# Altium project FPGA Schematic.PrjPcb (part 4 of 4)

## Sheet EVRHC008_VOUT_A_Phases 1-2-3.SchDoc
size 431 x 279 mm; Date: Not shown in title block; ApprovedBy: Not shown in title block; CheckedBy: Not shown in title block; Author: Not shown in title block; CompanyName: Not shown in title block; Engineer: Not shown in title block; Organization: Not shown in title block; Address1: Not shown in title block; Address2: Not shown in title block; Address3: Not shown in title block; Address4: Not shown in title block; DocumentNumber: 4; Revision: Use project parameter SCH_Rev; SheetNumber: 4; SheetTotal: 17; PageSetup: Record=PageOptions¦CenterHorizontal=True¦CenterVertical=True¦PrintScale=1.00¦XCorrection=1.00¦YCorrection=1.00¦PrintKind=0¦BorderSize=5000000¦LeftOffset=0¦BottomOffset=0¦Orientation=2¦PaperLength=1000¦PaperWidth=1000¦Scale=100¦PaperSource=15¦PrintQuality=600¦MediaType=1¦DitherType=10¦PaperKind=Letter¦PrintScaleMode=1
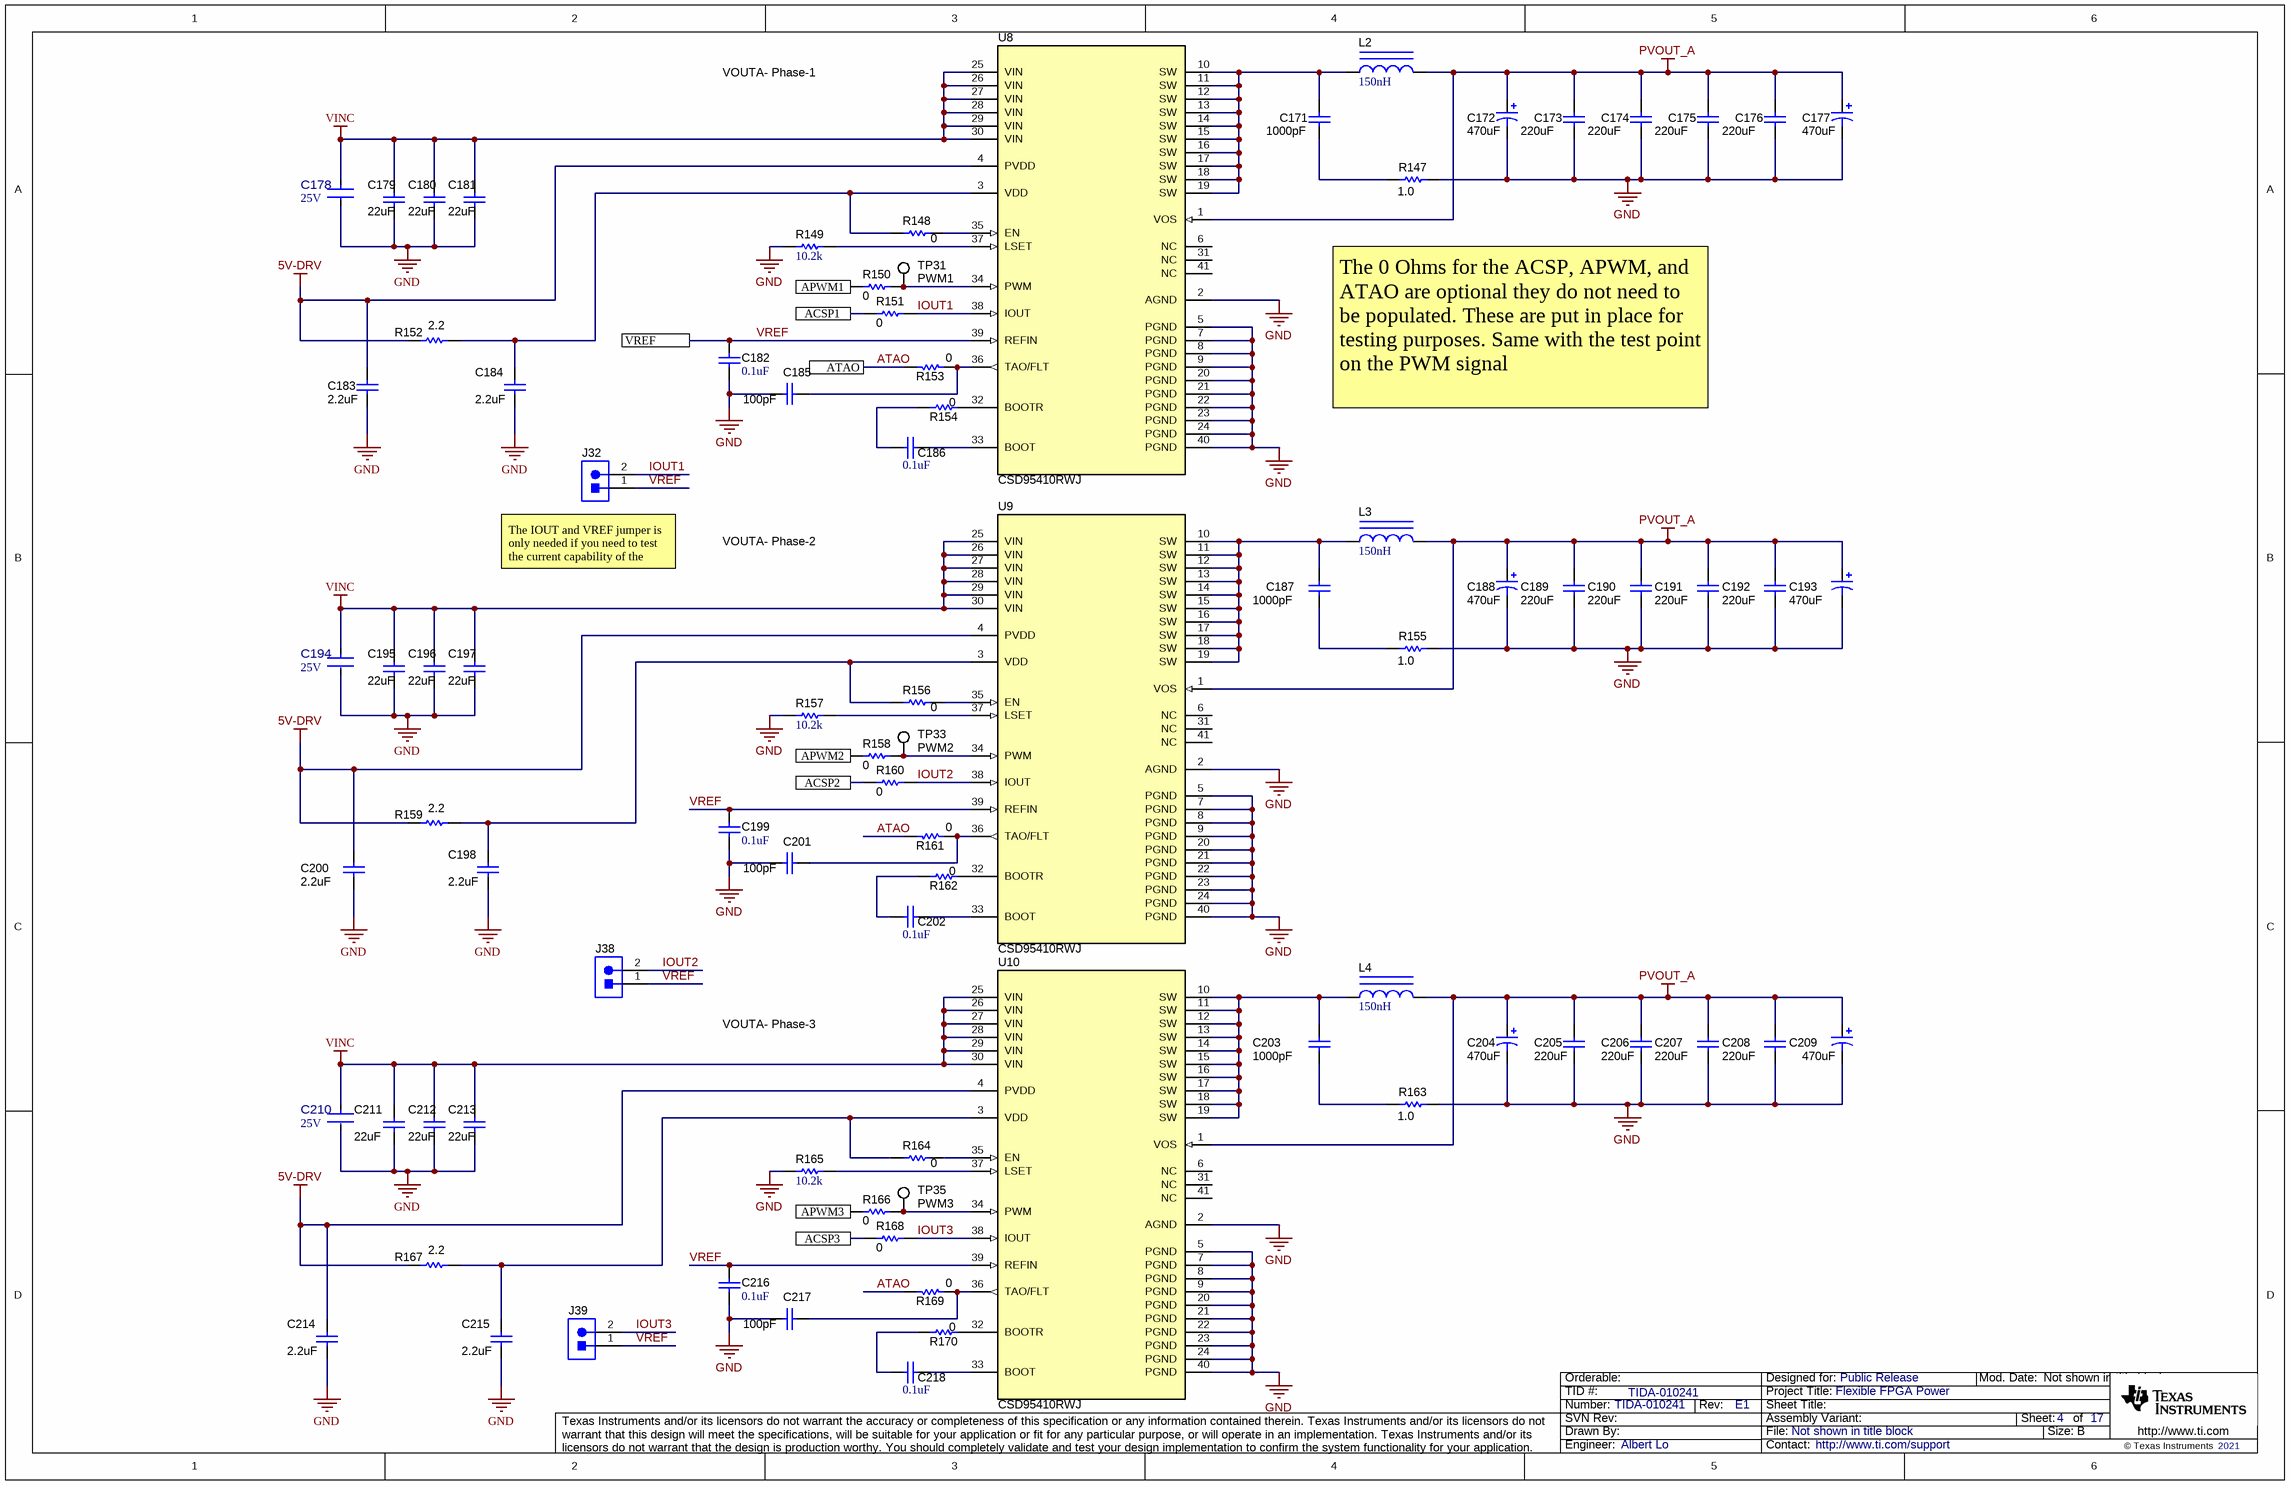
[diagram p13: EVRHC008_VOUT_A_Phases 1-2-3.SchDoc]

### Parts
C171  ValueDisplayed: 1000pF  [0402S]  (hidden comment: GRM155R71H102KA01D)
C172  ValueDisplayed: 470uF  [GX_2TERM]  (hidden comment: EEF-GX0E471R)
C173  ValueDisplayed: 220uF  [1206_190L]  (hidden comment: GRM31CR60G227ME11L)
C174  ValueDisplayed: 220uF  [1206_190L]  (hidden comment: GRM31CR60G227ME11L)
C175  ValueDisplayed: 220uF  [1206_190L]  (hidden comment: GRM31CR60G227ME11L)
C176  ValueDisplayed: 220uF  [1206_190L]  (hidden comment: GRM31CR60G227ME11L)
C177  ValueDisplayed: 470uF  [GX_2TERM]  (hidden comment: EEF-GX0E471R)
C178  VDC_V: 25V  [FP-GRM155C81E105KE11D_0402-MFG]  (hidden comment: GRM155C81E105KE11D)
C179  ValueDisplayed: 22uF  [0805L]  (hidden comment: Capacitor)
C180  ValueDisplayed: 22uF  [0805L]  (hidden comment: Capacitor)
C181  ValueDisplayed: 22uF  [0805L]  (hidden comment: Capacitor)
C182  ValueDisplayed: 0.1uF  [0402S]  (hidden comment: GCM155R71H104KE02D)
C183  ValueDisplayed: 2.2uF  [0402S]  (hidden comment: Capacitor)
C184  ValueDisplayed: 2.2uF  [0402S]  (hidden comment: Capacitor)
C185  ValueDisplayed: 100pF  [0402S]  (hidden comment: Capacitor)
C186  ValueDisplayed: 0.1uF  [0402S]  (hidden comment: GCM155R71H104KE02D)
C187  ValueDisplayed: 1000pF  [0402S]  (hidden comment: GRM155R71H102KA01D)
C188  ValueDisplayed: 470uF  [GX_2TERM]  (hidden comment: EEF-GX0E471R)
C189  ValueDisplayed: 220uF  [1206_190L]  (hidden comment: GRM31CR60G227ME11L)
C190  ValueDisplayed: 220uF  [1206_190L]  (hidden comment: GRM31CR60G227ME11L)
C191  ValueDisplayed: 220uF  [1206_190L]  (hidden comment: GRM31CR60G227ME11L)
C192  ValueDisplayed: 220uF  [1206_190L]  (hidden comment: GRM31CR60G227ME11L)
C193  ValueDisplayed: 470uF  [GX_2TERM]  (hidden comment: EEF-GX0E471R)
C194  VDC_V: 25V  [FP-GRM155C81E105KE11D_0402-MFG]  (hidden comment: GRM155C81E105KE11D)
C195  ValueDisplayed: 22uF  [0805L]  (hidden comment: Capacitor)
C196  ValueDisplayed: 22uF  [0805L]  (hidden comment: Capacitor)
C197  ValueDisplayed: 22uF  [0805L]  (hidden comment: Capacitor)
C198  ValueDisplayed: 2.2uF  [0402S]  (hidden comment: Capacitor)
C199  ValueDisplayed: 0.1uF  [0402S]  (hidden comment: GCM155R71H104KE02D)
C200  ValueDisplayed: 2.2uF  [0402S]  (hidden comment: Capacitor)
C201  ValueDisplayed: 100pF  [0402S]  (hidden comment: Capacitor)
C202  ValueDisplayed: 0.1uF  [0402S]  (hidden comment: GCM155R71H104KE02D)
C203  ValueDisplayed: 1000pF  [0402S]  (hidden comment: GRM155R71H102KA01D)
C204  ValueDisplayed: 470uF  [GX_2TERM]  (hidden comment: EEF-GX0E471R)
C205  ValueDisplayed: 220uF  [1206_190L]  (hidden comment: GRM31CR60G227ME11L)
C206  ValueDisplayed: 220uF  [1206_190L]  (hidden comment: GRM31CR60G227ME11L)
C207  ValueDisplayed: 220uF  [1206_190L]  (hidden comment: GRM31CR60G227ME11L)
C208  ValueDisplayed: 220uF  [1206_190L]  (hidden comment: GRM31CR60G227ME11L)
C209  ValueDisplayed: 470uF  [GX_2TERM]  (hidden comment: EEF-GX0E471R)
C210  VDC_V: 25V  [FP-GRM155C81E105KE11D_0402-MFG]  (hidden comment: GRM155C81E105KE11D)
C211  ValueDisplayed: 22uF  [0805L]  (hidden comment: Capacitor)
C212  ValueDisplayed: 22uF  [0805L]  (hidden comment: Capacitor)
C213  ValueDisplayed: 22uF  [0805L]  (hidden comment: Capacitor)
C214  ValueDisplayed: 2.2uF  [0402S]  (hidden comment: Capacitor)
C215  ValueDisplayed: 2.2uF  [0402S]  (hidden comment: Capacitor)
C216  ValueDisplayed: 0.1uF  [0402S]  (hidden comment: GCM155R71H104KE02D)
C217  ValueDisplayed: 100pF  [0402S]  (hidden comment: Capacitor)
C218  ValueDisplayed: 0.1uF  [0402S]  (hidden comment: GCM155R71H104KE02D)
J32  TSW-102-07-G-S  [TSW-102-07-G-S]  (value not drawn)
J38  TSW-102-07-G-S  [TSW-102-07-G-S]  (value not drawn)
J39  TSW-102-07-G-S  [TSW-102-07-G-S]  (value not drawn)
L2  ValueDisplayed: 150nH  [SLR1050]  (hidden comment: SLR1050A-151KEB)
L3  ValueDisplayed: 150nH  [SLR1050]  (hidden comment: SLR1050A-151KEB)
L4  ValueDisplayed: 150nH  [SLR1050]  (hidden comment: SLR1050A-151KEB)
R147  ValueDisplayed: 1.0  [0603S]  (hidden comment: CRCW06031R00JNEA)
R148  ValueDisplayed: 0  [0402S]  (hidden comment: CRCW04020000Z0ED)
R149  ValueDisplayed: 10.2k  [0402S]  (hidden comment: ERA-2AEB1022X)
R150  ValueDisplayed: 0  [0402S]  (hidden comment: CRCW04020000Z0ED)
R151  ValueDisplayed: 0  [0402S]  (hidden comment: CRCW04020000Z0ED)
R152  value 2.2  [0402S]  (hidden comment: CRCW04022R20JNED)
R153  ValueDisplayed: 0  [0402S]  (hidden comment: CRCW04020000Z0ED)
R154  value 0  [0402S]  (hidden comment: CRCW04020000Z0ED)
R155  ValueDisplayed: 1.0  [0603S]  (hidden comment: CRCW06031R00JNEA)
R156  ValueDisplayed: 0  [0402S]  (hidden comment: CRCW04020000Z0ED)
R157  ValueDisplayed: 10.2k  [0402S]  (hidden comment: ERA-2AEB1022X)
R158  ValueDisplayed: 0  [0402S]  (hidden comment: CRCW04020000Z0ED)
R159  value 2.2  [0402S]  (hidden comment: CRCW04022R20JNED)
R160  ValueDisplayed: 0  [0402S]  (hidden comment: CRCW04020000Z0ED)
R161  ValueDisplayed: 0  [0402S]  (hidden comment: CRCW04020000Z0ED)
R162  value 0  [0402S]  (hidden comment: CRCW04020000Z0ED)
R163  ValueDisplayed: 1.0  [0603S]  (hidden comment: CRCW06031R00JNEA)
R164  ValueDisplayed: 0  [0402S]  (hidden comment: CRCW04020000Z0ED)
R165  ValueDisplayed: 10.2k  [0402S]  (hidden comment: ERA-2AEB1022X)
R166  ValueDisplayed: 0  [0402S]  (hidden comment: CRCW04020000Z0ED)
R167  value 2.2  [0402S]  (hidden comment: CRCW04022R20JNED)
R168  ValueDisplayed: 0  [0402S]  (hidden comment: CRCW04020000Z0ED)
R169  ValueDisplayed: 0  [0402S]  (hidden comment: CRCW04020000Z0ED)
R170  value 0  [0402S]  (hidden comment: CRCW04020000Z0ED)
TP31  PWM1  [Keystone5007]
TP33  PWM2  [Keystone5007]
TP35  PWM3  [Keystone5007]
U8  CSD95410RWJ  [RWJ0041A]
U9  CSD95410RWJ  [RWJ0041A]
U10  CSD95410RWJ  [RWJ0041A]

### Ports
ACSP1, ACSP2, ACSP3, APWM1, APWM2, APWM3, ATAO, VREF

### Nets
5V-DRV: C183.1 C200.1 C214.1 R152.1 R159.1 R167.1 U8.4(PVDD) U9.4(PVDD) U10.4(PVDD)
GND: C172.2(-) C173.2 C174.2 C175.2 C176.2 C177.2(-) C178.2 C179.2 C180.2 C181.2 C182.1 C183.2 C184.2 C185.1 C188.2(-) C189.2 C190.2 C191.2 C192.2 C193.2(-) C194.2 C195.2 C196.2 C197.2 C198.2 C199.1 C200.2 C201.1 C204.2(-) C205.2 C206.2 C207.2 C208.2 C209.2(-) C210.2 C211.2 C212.2 C213.2 C214.2 C215.2 C216.1 C217.1 R147.1 R149.1 R155.1 R157.1 R163.1 R165.1 U8.2(AGND) U8.5(PGND) U8.7(PGND) U8.8(PGND) U8.9(PGND) U8.20(PGND) U8.21(PGND) U8.22(PGND) U8.23(PGND) U8.24(PGND) U8.40(PGND) U9.2(AGND) U9.5(PGND) U9.7(PGND) U9.8(PGND) U9.9(PGND) U9.20(PGND) U9.21(PGND) U9.22(PGND) U9.23(PGND) U9.24(PGND) U9.40(PGND) U10.2(AGND) U10.5(PGND) U10.7(PGND) U10.8(PGND) U10.9(PGND) U10.20(PGND) U10.21(PGND) U10.22(PGND) U10.23(PGND) U10.24(PGND) U10.40(PGND)
PVOUT_A: C172.1(+) C173.1 C174.1 C175.1 C176.1 C177.1(+) C188.1(+) C189.1 C190.1 C191.1 C192.1 C193.1(+) C204.1(+) C205.1 C206.1 C207.1 C208.1 C209.1(+) L2.2 L3.2 L4.2 U8.1(VOS) U9.1(VOS) U10.1(VOS)
VINC: C178.1 C179.1 C180.1 C181.1 C194.1 C195.1 C196.1 C197.1 C210.1 C211.1 C212.1 C213.1 U8.25(VIN) U8.26(VIN) U8.27(VIN) U8.28(VIN) U8.29(VIN) U8.30(VIN) U9.25(VIN) U9.26(VIN) U9.27(VIN) U9.28(VIN) U9.29(VIN) U9.30(VIN) U10.25(VIN) U10.26(VIN) U10.27(VIN) U10.28(VIN) U10.29(VIN) U10.30(VIN)
ACSP1: R151.2 ; port ACSP1
ACSP2: R160.2 ; port ACSP2
ACSP3: R168.2 ; port ACSP3
APWM1: R150.2 ; port APWM1
APWM2: R158.2 ; port APWM2
APWM3: R166.2 ; port APWM3
ATAO: R153.1 R161.1 R169.1 ; port ATAO
IOUT1: J32.2 R151.1 U8.38(IOUT)
IOUT2: J38.2 R160.1 U9.38(IOUT)
IOUT3: J39.2 R168.1 U10.38(IOUT)
VREF: C182.2 C199.2 C216.2 J32.1 J38.1 J39.1 U8.39(REFIN) U9.39(REFIN) U10.39(REFIN) ; port VREF
NetC171_1: C171.1 L2.1 U8.10(SW) U8.11(SW) U8.12(SW) U8.13(SW) U8.14(SW) U8.15(SW) U8.16(SW) U8.17(SW) U8.18(SW) U8.19(SW)
NetC171_2: C171.2 R147.2
NetC184_1: C184.1 R148.2 R152.2 U8.3(VDD)
NetC185_2: C185.2 R153.2 U8.36(TAO/FLT)
NetC186_1: C186.1 R154.2
NetC186_2: C186.2 U8.33(BOOT)
NetC187_1: C187.1 L3.1 U9.10(SW) U9.11(SW) U9.12(SW) U9.13(SW) U9.14(SW) U9.15(SW) U9.16(SW) U9.17(SW) U9.18(SW) U9.19(SW)
NetC187_2: C187.2 R155.2
NetC198_1: C198.1 R156.2 R159.2 U9.3(VDD)
NetC201_2: C201.2 R161.2 U9.36(TAO/FLT)
NetC202_1: C202.1 R162.2
NetC202_2: C202.2 U9.33(BOOT)
NetC203_1: C203.1 L4.1 U10.10(SW) U10.11(SW) U10.12(SW) U10.13(SW) U10.14(SW) U10.15(SW) U10.16(SW) U10.17(SW) U10.18(SW) U10.19(SW)
NetC203_2: C203.2 R163.2
NetC215_1: C215.1 R164.2 R167.2 U10.3(VDD)
NetC217_2: C217.2 R169.2 U10.36(TAO/FLT)
NetC218_1: C218.1 R170.2
NetC218_2: C218.2 U10.33(BOOT)
NetR148_1: R148.1 U8.35(EN)
NetR149_2: R149.2 U8.37(LSET)
NetR150_1: R150.1 TP31.1 U8.34(PWM)
NetR154_1: R154.1 U8.32(BOOTR)
NetR156_1: R156.1 U9.35(EN)
NetR157_2: R157.2 U9.37(LSET)
NetR158_1: R158.1 TP33.1 U9.34(PWM)
NetR162_1: R162.1 U9.32(BOOTR)
NetR164_1: R164.1 U10.35(EN)
NetR165_2: R165.2 U10.37(LSET)
NetR166_1: R166.1 TP35.1 U10.34(PWM)
NetR170_1: R170.1 U10.32(BOOTR)

Not connected (* = marked no-connect by the designer): U8 6(NC) 31(NC) 41(NC); U9 6(NC) 31(NC) 41(NC); U10 6(NC) 31(NC) 41(NC)

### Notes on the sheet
- VOUTA- Phase-1
- The 0 Ohms for the ACSP, APWM, and ATAO are optional they do not need to be populated. These are put in place for testing purposes. Same with the test point on the PWM signal
- (near J32) The IOUT and VREF jumper is only needed if you need to test the current capability of the controller.
- VOUTA- Phase-2
- VOUTA- Phase-3

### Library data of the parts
C171 C187 C203 = CMP-0006673-2: CAP, CERM, 1000 pF, 50 V, +/- 10%, X7R, 0402; Manufacturer: MuRata; Polarized: N; Value: 1000pF; U/M: EA; Cap_F: 1nF; Value1: Unknown; VDC_V: 50V; TaMin_C: -55°C; TaMax_C: 125°C; Cap_Case: 0402; AEC Category: Q200; SizeArea_mm2: 0.5; SizeAreaWB_mm2: 3; SizeX_mm: 1; SizeZ_mm: 0.6
C172 C177 C188 C193 C204 C209 = CMP-0012242-3: CAP, Aluminum Polymer, 470 uF, 2.5 V, +/- 20%, 0.003 ohm, SMD_7.3x1.9x4.3mm SMD; Manufacturer: Panasonic; Value: 470uF; Polarized: Y; CompType: Capacitor; Cap_F: 470µF; VDC_V: 2.5V; ESR_ohm: 3m; IRMS_A: 10.2A; TaMin_C: -40°C; TaMax_C: 105°C; AEC Category: Q200; AEC Qualified: N
C173-C176 C189-C192 C205-C208 = CMP-0008932-2: CAP, CERM, 220 uF, 4 V, +/- 20%, X5R, 1206_190; Manufacturer: MuRata; Polarized: N; Value: 220uF; U/M: EA; Cap_F: 220µF; Value1: Unknown; VDC_V: 4V; TaMin_C: -55°C; TaMax_C: 85°C; Cap_Case: 1206; SizeArea_mm2: 5.12; SizeAreaWB_mm2: 10.92; SizeX_mm: 3.2; SizeY_mm: 1.6; SizeZ_mm: 1.9; AEC Category: Q200
C178 C194 C210 = CMP-0086485-1: CAP CER 1UF 25V X6S 0402; Manufacturer: Murata; AEC Qualified: No; Cap_F: 1µF; Tolerance_%: 10%; TempCo: 22%; SizeZ_mm: 0.6mm; Symbol Name: SYM-GRM155C81E105KE11D
C179-C181 C195-C197 C211-C213 = CMP-0008293-2: CAP, CERM, 22 uF, 16 V, +/- 20%, X5R, 0805; PartNumber: GRM21BR61C226ME44; Manufacturer: MuRata; Polarized: N; Value: 22uF; U/M: EA; Cap_F: 22µF; Value1: Unknown; VDC_V: 16V; TaMin_C: -55°C; TaMax_C: 85°C; Cap_Case: 0805; AEC Category: Q200; SizeArea_mm2: 2.5; SizeAreaWB_mm2: 6.75; SizeX_mm: 2; SizeY_mm: 1.25; SizeZ_mm: 1.45
C182 C186 C199 C202 C216 C218 = CMP-0006356-2: CAP, CERM, 0.1 uF, 50 V, +/- 10%, X7R, AEC-Q200 Grade 1, 0402; Manufacturer: MuRata; TaMin_C: -55°C; Polarized: N; SizeAreaWB_mm2: 3; Value1: Unknown; U/M: EA; Value: 0.1uF; TaMax_C: 125°C; SizeZ_mm: 0.6; SizeX_mm: 1; SizeY_mm: 0.5; Cap_Case: 0402; Value2: 50V; AEC Qualified: Y; Cap_F: 100nF; AEC Category: Q200
C183 C184 C198 C200 C214 C215 = CMP-0006263-2: CAP, CERM, 2.2 uF, 10 V, +/- 10%, X5R, 0402; PartNumber: C1005X5R1A225K050BC; Manufacturer: TDK; Polarized: N; Value: 2.2uF; U/M: EA; Cap_F: 2.2µF; Value1: Unknown; VDC_V: 10V; TaMin_C: -55°C; TaMax_C: 85°C; Cap_Case: 0402; AEC Category: Q200; SizeArea_mm2: 0.5; SizeAreaWB_mm2: 3; SizeX_mm: 1; SizeZ_mm: 0.6
C185 C201 C217 = CMP-0006233-2: CAP, CERM, 100 pF, 25 V, +/- 5%, C0G/NP0, 0402; PartNumber: C0402C101J3GACTU; Manufacturer: Kemet; Polarized: N; Value: 100pF; U/M: EA; Value1: Unknown; VDC_V: 25V; TaMin_C: -55°C; TaMax_C: 125°C; Cap_Case: 0402; AEC Category: Q200; SizeArea_mm2: 0.5; SizeAreaWB_mm2: 3; SizeX_mm: 1; SizeZ_mm: 0.6
J32 J38 J39 = CMP-0075405-3: Header, 100mil, 2x1, Gold, TH; Manufacturer: Samtec; Pitch_mm: 2.54; Gender: Male; Shrouded: N; Row_Count: 1; Current_A: 6.3A; Voltage_V: 550V; Cert_CSA: Y; Green_Lifecycle: Active; Green_REACh: Passed
L2-L4 = CMP-0060908-1: Inductor, Shielded, Ferrite, 150 nH, 51 A, 0.0004 ohm, SMD; Manufacturer: Coilcraft; Value: 150nH; Imax_A: 51A; Irms: 77.1A @ 40C rise; Isat: 51A @ 20% inductance drop; DCR_ohm: 400µ; AEC Category: Q200; AEC Qualified: N; SizeAreaWB_mm2: 109.8; SizeArea_mm2: 71.4; SizeX_mm: 10.2; SizeY_mm: 7; SizeZ_mm: 4.95
R147 R155 R163 = CMP-0025743-4: RES, 1.0, 5%, 0.1 W, AEC-Q200 Grade 0, 0603; Manufacturer: Vishay-Dale; Value: 1.0; Res_ohm: 1; Value_Code: 1R00; Power_W: 100mW; Value2: 0.1W; VDC_V: 75V; TempCo: 200 ppm/C; EIA_Code: E24; AEC Category: Q200; AEC Grade: 0; AEC Qualified: Y; SizeArea_mm2: 1.28; SizeX_mm: 1.6; SizeY_mm: 0.8
R148 R150 R151 R156 R158 R160 R164 R166 R168 = CMP-0026822-3: RES, 0, 5%, 0.063 W, AEC-Q200 Grade 0, 0402; Manufacturer: Vishay-Dale; Value: 0; Value_Code: 0000; Power_W: 63mW; Value2: 0.063W; VDC_V: 50V; TempCo: 200 ppm/C; EIA_Code: E24; SizeArea_mm2: 0.5; SizeX_mm: 1; SizeZ_mm: 0.6; AEC Category: Q200; AEC Qualified: Y
R149 R157 R165 = CMP-0085489-1: RES, 10.2 k, 0.1%, 0.063 W, AEC-Q200 Grade 1, 0402; Manufacturer: Panasonic; AEC Grade: 1; TempCo: 25 ppm/C; SizeZ_mm: 0.6; Value: 10.2k; Power_W: 63mW; SizeArea_mm2: 0.5; Value_Code: 10k2; Value2: 0.063W; AEC Category: Q200; SizeAreaWB_mm2: 3; EIA_Code: E192; AEC Qualified: Y
R152 R159 R167 = CMP-0026898-3: RES, 2.2, 5%, 0.063 W, AEC-Q200 Grade 0, 0402; Manufacturer: Vishay-Dale; Value_Code: 2R20; Power_W: 63mW; Value2: 0.063W; VDC_V: 50V; TempCo: 200 ppm/C; EIA_Code: E24; AEC Category: Q200; AEC Grade: 0; AEC Qualified: Y; SizeArea_mm2: 0.5; SizeX_mm: 1; SizeZ_mm: 0.6
R153 R161 R169 = CMP-0026822-3: RES, 0, 5%, 0.063 W, AEC-Q200 Grade 0, 0402; Manufacturer: Vishay-Dale; Value: 0; Value_Code: 0000; Power_W: 63mW; Value2: 0.063W; VDC_V: 50V; TempCo: 200 ppm/C; EIA_Code: E24; AEC Category: Q200; AEC Qualified: Y; SizeArea_mm2: 0.5; SizeX_mm: 1; SizeZ_mm: 0.6
R154 R162 R170 = CMP-0026822-3: RES, 0, 5%, 0.063 W, AEC-Q200 Grade 0, 0402; Manufacturer: Vishay-Dale; Value_Code: 0000; Power_W: 63mW; Value2: 0.063W; VDC_V: 50V; TempCo: 200 ppm/C; EIA_Code: E24; AEC Category: Q200; AEC Qualified: Y; SizeArea_mm2: 0.5; SizeX_mm: 1; SizeZ_mm: 0.6
TP31 TP33 TP35 = CMP-0055144-1: Test Point, Compact, White, TH; Manufacturer: Keystone; ContactFinish: Silver; CNHeader: FALSE; CT: TRUE; Green_Lifecycle: Active; Green_REACh: Passed
U8-U10 = CMP-0085794-1: Synchronous Buck NexFET Smart Power Stage, RWJ0041A (VQFN-CLIP-41); Alternate Manufacturer: Texas Instruments; SizeX_mm: 5; SizeAreaWB_mm2: 56; CompType: IC; SizeY_mm: 6; AEC Category: Q200; SizeZ_mm: 1.05; AEC Qualified: N; SizeArea_mm2: 30; Comments: Customer Supplied

## Sheet EVRHC008_VOUT_A_Phases 4-5-6.SchDoc
size 431 x 279 mm; Date: Not shown in title block; ApprovedBy: Not shown in title block; CheckedBy: Not shown in title block; Author: Not shown in title block; CompanyName: Not shown in title block; Engineer: Not shown in title block; Organization: Not shown in title block; Address1: Not shown in title block; Address2: Not shown in title block; Address3: Not shown in title block; Address4: Not shown in title block; DocumentNumber: 5; Revision: Use project parameter SCH_Rev; SheetNumber: 5; SheetTotal: 17; PageSetup: Record=PageOptions¦CenterHorizontal=True¦CenterVertical=True¦PrintScale=1.00¦XCorrection=1.00¦YCorrection=1.00¦PrintKind=0¦BorderSize=5000000¦LeftOffset=0¦BottomOffset=0¦Orientation=2¦PaperLength=1000¦PaperWidth=1000¦Scale=100¦PaperSource=15¦PrintQuality=600¦MediaType=1¦DitherType=10¦PaperKind=Letter¦PrintScaleMode=1
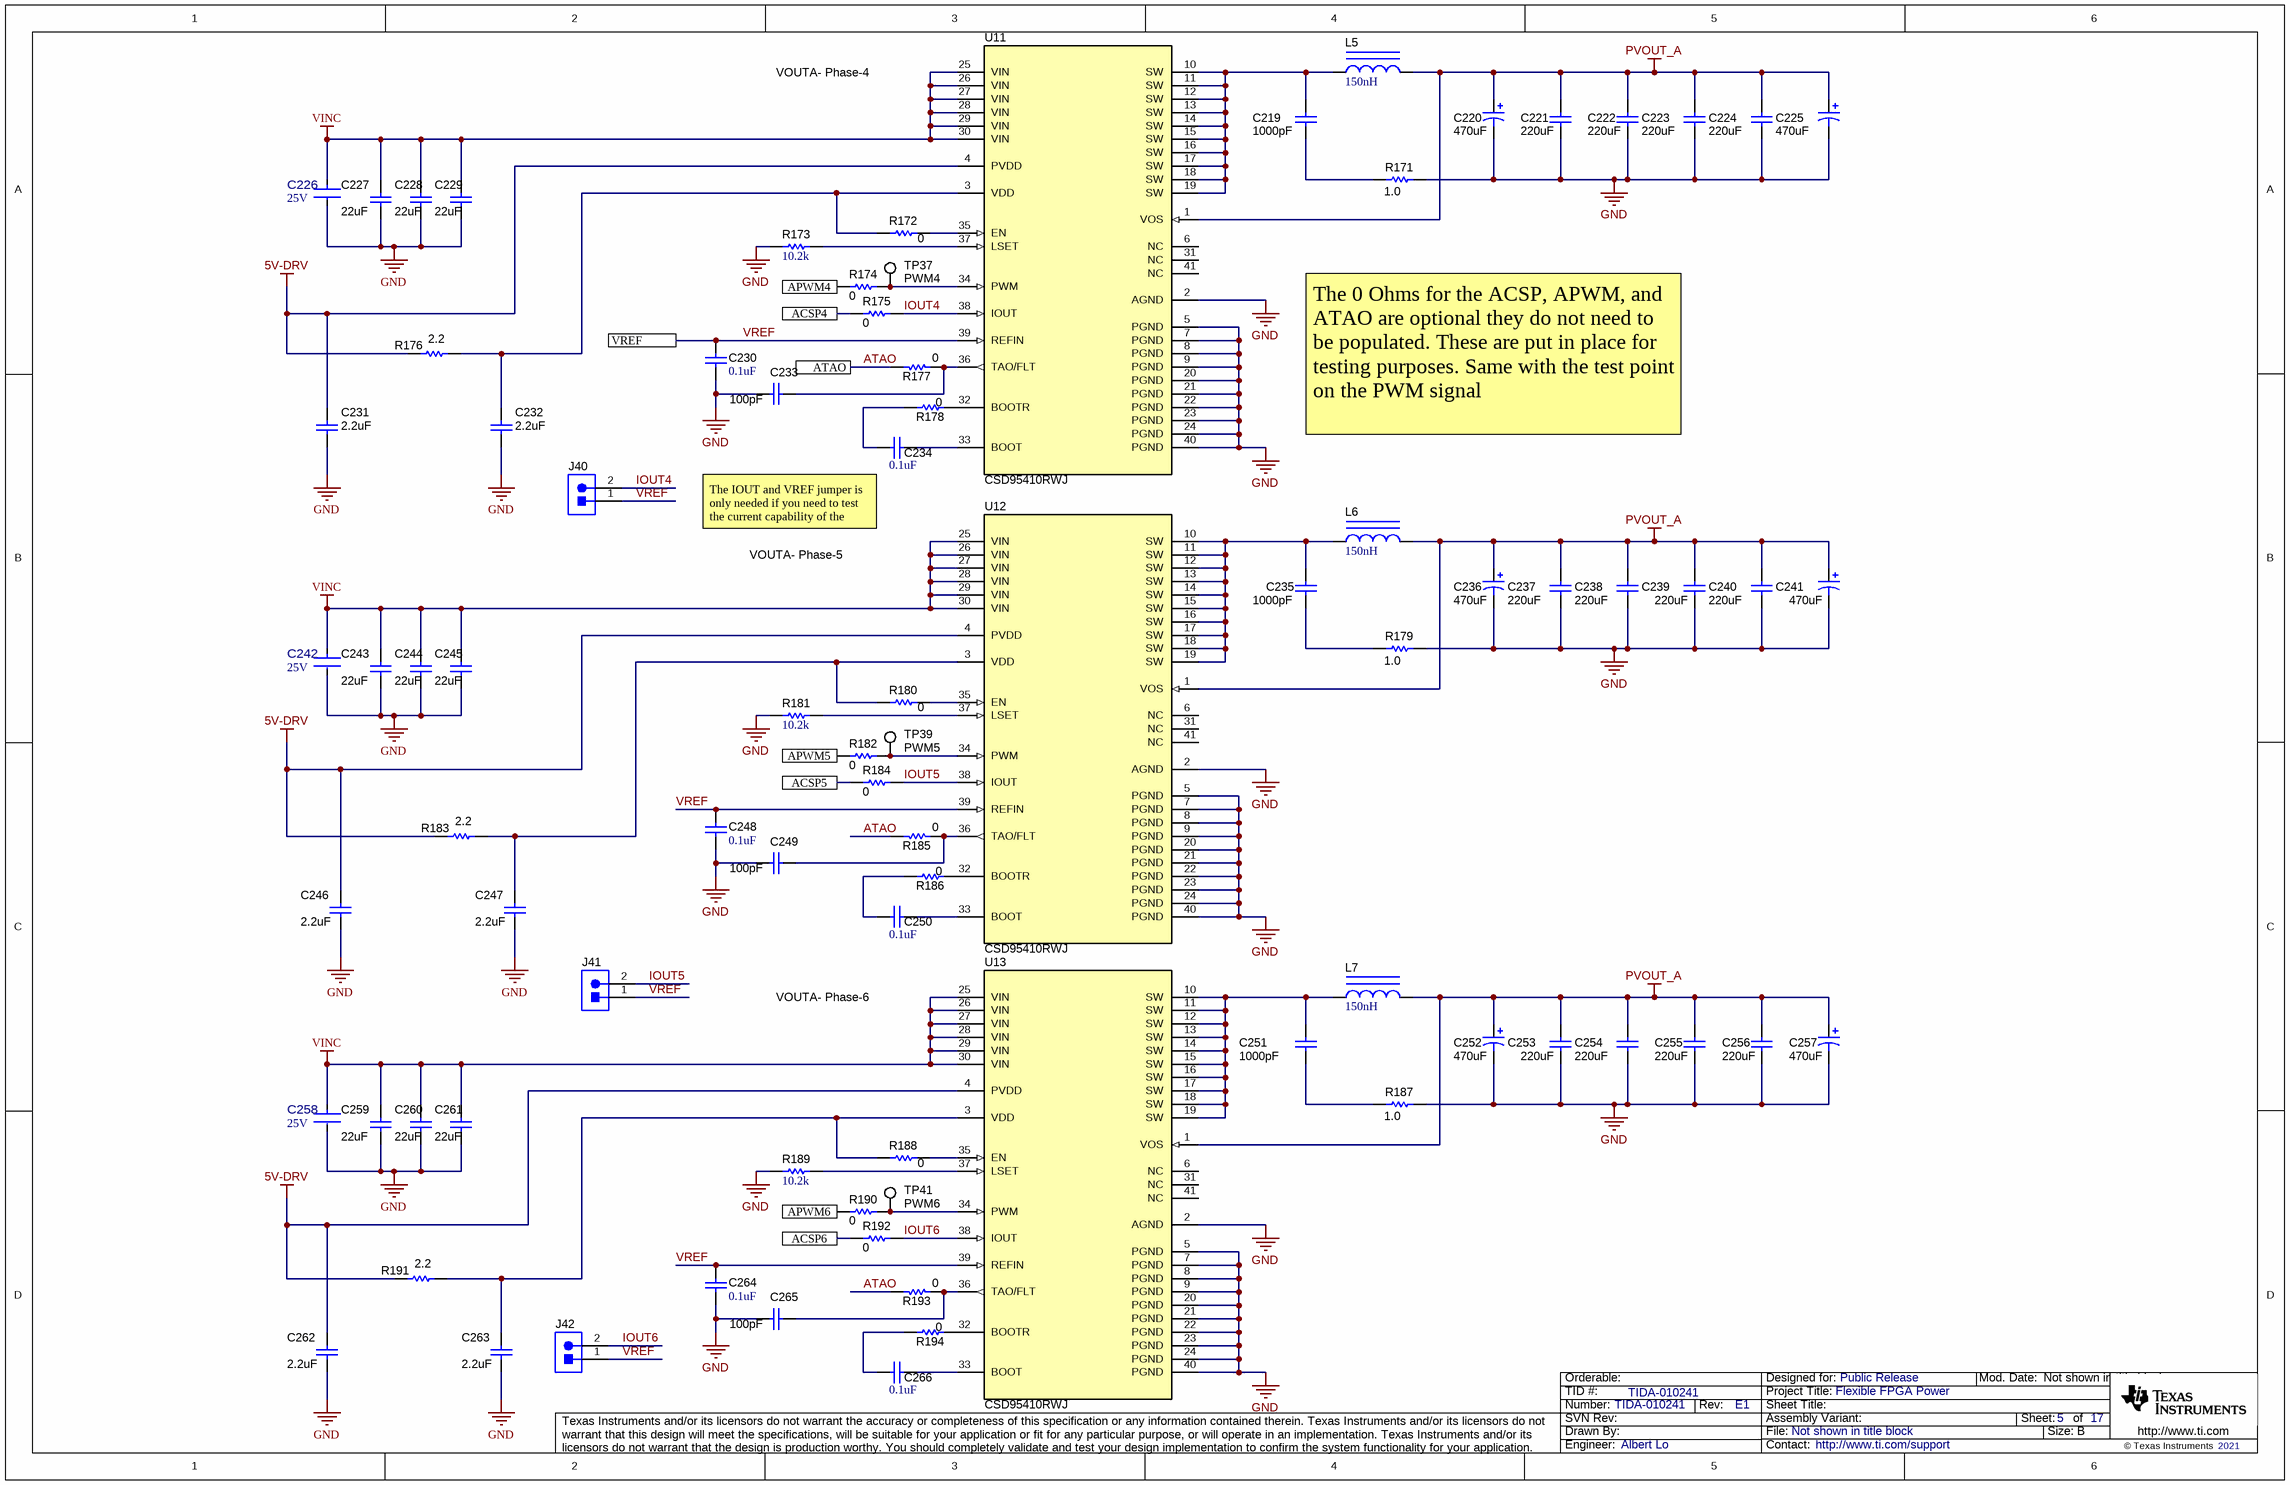
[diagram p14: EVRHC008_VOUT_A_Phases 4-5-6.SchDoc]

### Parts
C219  ValueDisplayed: 1000pF  [0402S]  (hidden comment: GRM155R71H102KA01D)
C220  ValueDisplayed: 470uF  [GX_2TERM]  (hidden comment: EEF-GX0E471R)
C221  ValueDisplayed: 220uF  [1206_190L]  (hidden comment: GRM31CR60G227ME11L)
C222  ValueDisplayed: 220uF  [1206_190L]  (hidden comment: GRM31CR60G227ME11L)
C223  ValueDisplayed: 220uF  [1206_190L]  (hidden comment: GRM31CR60G227ME11L)
C224  ValueDisplayed: 220uF  [1206_190L]  (hidden comment: GRM31CR60G227ME11L)
C225  ValueDisplayed: 470uF  [GX_2TERM]  (hidden comment: EEF-GX0E471R)
C226  VDC_V: 25V  [FP-GRM155C81E105KE11D_0402-MFG]  (hidden comment: GRM155C81E105KE11D)
C227  ValueDisplayed: 22uF  [0805L]  (hidden comment: Capacitor)
C228  ValueDisplayed: 22uF  [0805L]  (hidden comment: Capacitor)
C229  ValueDisplayed: 22uF  [0805L]  (hidden comment: Capacitor)
C230  ValueDisplayed: 0.1uF  [0402S]  (hidden comment: GCM155R71H104KE02D)
C231  ValueDisplayed: 2.2uF  [0402S]  (hidden comment: Capacitor)
C232  ValueDisplayed: 2.2uF  [0402S]  (hidden comment: Capacitor)
C233  ValueDisplayed: 100pF  [0402S]  (hidden comment: Capacitor)
C234  ValueDisplayed: 0.1uF  [0402S]  (hidden comment: GCM155R71H104KE02D)
C235  ValueDisplayed: 1000pF  [0402S]  (hidden comment: GRM155R71H102KA01D)
C236  ValueDisplayed: 470uF  [GX_2TERM]  (hidden comment: EEF-GX0E471R)
C237  ValueDisplayed: 220uF  [1206_190L]  (hidden comment: GRM31CR60G227ME11L)
C238  ValueDisplayed: 220uF  [1206_190L]  (hidden comment: GRM31CR60G227ME11L)
C239  ValueDisplayed: 220uF  [1206_190L]  (hidden comment: GRM31CR60G227ME11L)
C240  ValueDisplayed: 220uF  [1206_190L]  (hidden comment: GRM31CR60G227ME11L)
C241  ValueDisplayed: 470uF  [GX_2TERM]  (hidden comment: EEF-GX0E471R)
C242  VDC_V: 25V  [FP-GRM155C81E105KE11D_0402-MFG]  (hidden comment: GRM155C81E105KE11D)
C243  ValueDisplayed: 22uF  [0805L]  (hidden comment: Capacitor)
C244  ValueDisplayed: 22uF  [0805L]  (hidden comment: Capacitor)
C245  ValueDisplayed: 22uF  [0805L]  (hidden comment: Capacitor)
C246  ValueDisplayed: 2.2uF  [0402S]  (hidden comment: Capacitor)
C247  ValueDisplayed: 2.2uF  [0402S]  (hidden comment: Capacitor)
C248  ValueDisplayed: 0.1uF  [0402S]  (hidden comment: GCM155R71H104KE02D)
C249  ValueDisplayed: 100pF  [0402S]  (hidden comment: Capacitor)
C250  ValueDisplayed: 0.1uF  [0402S]  (hidden comment: GCM155R71H104KE02D)
C251  ValueDisplayed: 1000pF  [0402S]  (hidden comment: GRM155R71H102KA01D)
C252  ValueDisplayed: 470uF  [GX_2TERM]  (hidden comment: EEF-GX0E471R)
C253  ValueDisplayed: 220uF  [1206_190L]  (hidden comment: GRM31CR60G227ME11L)
C254  ValueDisplayed: 220uF  [1206_190L]  (hidden comment: GRM31CR60G227ME11L)
C255  ValueDisplayed: 220uF  [1206_190L]  (hidden comment: GRM31CR60G227ME11L)
C256  ValueDisplayed: 220uF  [1206_190L]  (hidden comment: GRM31CR60G227ME11L)
C257  ValueDisplayed: 470uF  [GX_2TERM]  (hidden comment: EEF-GX0E471R)
C258  VDC_V: 25V  [FP-GRM155C81E105KE11D_0402-MFG]  (hidden comment: GRM155C81E105KE11D)
C259  ValueDisplayed: 22uF  [0805L]  (hidden comment: Capacitor)
C260  ValueDisplayed: 22uF  [0805L]  (hidden comment: Capacitor)
C261  ValueDisplayed: 22uF  [0805L]  (hidden comment: Capacitor)
C262  ValueDisplayed: 2.2uF  [0402S]  (hidden comment: Capacitor)
C263  ValueDisplayed: 2.2uF  [0402S]  (hidden comment: Capacitor)
C264  ValueDisplayed: 0.1uF  [0402S]  (hidden comment: GCM155R71H104KE02D)
C265  ValueDisplayed: 100pF  [0402S]  (hidden comment: Capacitor)
C266  ValueDisplayed: 0.1uF  [0402S]  (hidden comment: GCM155R71H104KE02D)
J40  TSW-102-07-G-S  [TSW-102-07-G-S]  (value not drawn)
J41  TSW-102-07-G-S  [TSW-102-07-G-S]  (value not drawn)
J42  TSW-102-07-G-S  [TSW-102-07-G-S]  (value not drawn)
L5  ValueDisplayed: 150nH  [SLR1050]  (hidden comment: SLR1050A-151KEB)
L6  ValueDisplayed: 150nH  [SLR1050]  (hidden comment: SLR1050A-151KEB)
L7  ValueDisplayed: 150nH  [SLR1050]  (hidden comment: SLR1050A-151KEB)
R171  ValueDisplayed: 1.0  [0603S]  (hidden comment: CRCW06031R00JNEA)
R172  ValueDisplayed: 0  [0402S]  (hidden comment: CRCW04020000Z0ED)
R173  ValueDisplayed: 10.2k  [0402S]  (hidden comment: ERA-2AEB1022X)
R174  ValueDisplayed: 0  [0402S]  (hidden comment: CRCW04020000Z0ED)
R175  ValueDisplayed: 0  [0402S]  (hidden comment: CRCW04020000Z0ED)
R176  value 2.2  [0402S]  (hidden comment: CRCW04022R20JNED)
R177  ValueDisplayed: 0  [0402S]  (hidden comment: CRCW04020000Z0ED)
R178  value 0  [0402S]  (hidden comment: CRCW04020000Z0ED)
R179  ValueDisplayed: 1.0  [0603S]  (hidden comment: CRCW06031R00JNEA)
R180  ValueDisplayed: 0  [0402S]  (hidden comment: CRCW04020000Z0ED)
R181  ValueDisplayed: 10.2k  [0402S]  (hidden comment: ERA-2AEB1022X)
R182  ValueDisplayed: 0  [0402S]  (hidden comment: CRCW04020000Z0ED)
R183  value 2.2  [0402S]  (hidden comment: CRCW04022R20JNED)
R184  ValueDisplayed: 0  [0402S]  (hidden comment: CRCW04020000Z0ED)
R185  ValueDisplayed: 0  [0402S]  (hidden comment: CRCW04020000Z0ED)
R186  value 0  [0402S]  (hidden comment: CRCW04020000Z0ED)
R187  ValueDisplayed: 1.0  [0603S]  (hidden comment: CRCW06031R00JNEA)
R188  ValueDisplayed: 0  [0402S]  (hidden comment: CRCW04020000Z0ED)
R189  ValueDisplayed: 10.2k  [0402S]  (hidden comment: ERA-2AEB1022X)
R190  ValueDisplayed: 0  [0402S]  (hidden comment: CRCW04020000Z0ED)
R191  value 2.2  [0402S]  (hidden comment: CRCW04022R20JNED)
R192  ValueDisplayed: 0  [0402S]  (hidden comment: CRCW04020000Z0ED)
R193  ValueDisplayed: 0  [0402S]  (hidden comment: CRCW04020000Z0ED)
R194  value 0  [0402S]  (hidden comment: CRCW04020000Z0ED)
TP37  PWM4  [Keystone5007]
TP39  PWM5  [Keystone5007]
TP41  PWM6  [Keystone5007]
U11  CSD95410RWJ  [RWJ0041A]
U12  CSD95410RWJ  [RWJ0041A]
U13  CSD95410RWJ  [RWJ0041A]

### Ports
ACSP4, ACSP5, ACSP6, APWM4, APWM5, APWM6, ATAO, VREF

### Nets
5V-DRV: C231.1 C246.1 C262.1 R176.1 R183.1 R191.1 U11.4(PVDD) U12.4(PVDD) U13.4(PVDD)
GND: C220.2(-) C221.2 C222.2 C223.2 C224.2 C225.2(-) C226.2 C227.2 C228.2 C229.2 C230.1 C231.2 C232.2 C233.1 C236.2(-) C237.2 C238.2 C239.2 C240.2 C241.2(-) C242.2 C243.2 C244.2 C245.2 C246.2 C247.2 C248.1 C249.1 C252.2(-) C253.2 C254.2 C255.2 C256.2 C257.2(-) C258.2 C259.2 C260.2 C261.2 C262.2 C263.2 C264.1 C265.1 R171.1 R173.1 R179.1 R181.1 R187.1 R189.1 U11.2(AGND) U11.5(PGND) U11.7(PGND) U11.8(PGND) U11.9(PGND) U11.20(PGND) U11.21(PGND) U11.22(PGND) U11.23(PGND) U11.24(PGND) U11.40(PGND) U12.2(AGND) U12.5(PGND) U12.7(PGND) U12.8(PGND) U12.9(PGND) U12.20(PGND) U12.21(PGND) U12.22(PGND) U12.23(PGND) U12.24(PGND) U12.40(PGND) U13.2(AGND) U13.5(PGND) U13.7(PGND) U13.8(PGND) U13.9(PGND) U13.20(PGND) U13.21(PGND) U13.22(PGND) U13.23(PGND) U13.24(PGND) U13.40(PGND)
PVOUT_A: C220.1(+) C221.1 C222.1 C223.1 C224.1 C225.1(+) C236.1(+) C237.1 C238.1 C239.1 C240.1 C241.1(+) C252.1(+) C253.1 C254.1 C255.1 C256.1 C257.1(+) L5.2 L6.2 L7.2 U11.1(VOS) U12.1(VOS) U13.1(VOS)
VINC: C226.1 C227.1 C228.1 C229.1 C242.1 C243.1 C244.1 C245.1 C258.1 C259.1 C260.1 C261.1 U11.25(VIN) U11.26(VIN) U11.27(VIN) U11.28(VIN) U11.29(VIN) U11.30(VIN) U12.25(VIN) U12.26(VIN) U12.27(VIN) U12.28(VIN) U12.29(VIN) U12.30(VIN) U13.25(VIN) U13.26(VIN) U13.27(VIN) U13.28(VIN) U13.29(VIN) U13.30(VIN)
ACSP4: R175.2 ; port ACSP4
ACSP5: R184.2 ; port ACSP5
ACSP6: R192.2 ; port ACSP6
APWM4: R174.2 ; port APWM4
APWM5: R182.2 ; port APWM5
APWM6: R190.2 ; port APWM6
ATAO: R177.1 R185.1 R193.1 ; port ATAO
IOUT4: J40.2 R175.1 U11.38(IOUT)
IOUT5: J41.2 R184.1 U12.38(IOUT)
IOUT6: J42.2 R192.1 U13.38(IOUT)
VREF: C230.2 C248.2 C264.2 J40.1 J41.1 J42.1 U11.39(REFIN) U12.39(REFIN) U13.39(REFIN) ; port VREF
NetC219_1: C219.1 L5.1 U11.10(SW) U11.11(SW) U11.12(SW) U11.13(SW) U11.14(SW) U11.15(SW) U11.16(SW) U11.17(SW) U11.18(SW) U11.19(SW)
NetC219_2: C219.2 R171.2
NetC232_1: C232.1 R172.2 R176.2 U11.3(VDD)
NetC233_2: C233.2 R177.2 U11.36(TAO/FLT)
NetC234_1: C234.1 R178.2
NetC234_2: C234.2 U11.33(BOOT)
NetC235_1: C235.1 L6.1 U12.10(SW) U12.11(SW) U12.12(SW) U12.13(SW) U12.14(SW) U12.15(SW) U12.16(SW) U12.17(SW) U12.18(SW) U12.19(SW)
NetC235_2: C235.2 R179.2
NetC247_1: C247.1 R180.2 R183.2 U12.3(VDD)
NetC249_2: C249.2 R185.2 U12.36(TAO/FLT)
NetC250_1: C250.1 R186.2
NetC250_2: C250.2 U12.33(BOOT)
NetC251_1: C251.1 L7.1 U13.10(SW) U13.11(SW) U13.12(SW) U13.13(SW) U13.14(SW) U13.15(SW) U13.16(SW) U13.17(SW) U13.18(SW) U13.19(SW)
NetC251_2: C251.2 R187.2
NetC263_1: C263.1 R188.2 R191.2 U13.3(VDD)
NetC265_2: C265.2 R193.2 U13.36(TAO/FLT)
NetC266_1: C266.1 R194.2
NetC266_2: C266.2 U13.33(BOOT)
NetR172_1: R172.1 U11.35(EN)
NetR173_2: R173.2 U11.37(LSET)
NetR174_1: R174.1 TP37.1 U11.34(PWM)
NetR178_1: R178.1 U11.32(BOOTR)
NetR180_1: R180.1 U12.35(EN)
NetR181_2: R181.2 U12.37(LSET)
NetR182_1: R182.1 TP39.1 U12.34(PWM)
NetR186_1: R186.1 U12.32(BOOTR)
NetR188_1: R188.1 U13.35(EN)
NetR189_2: R189.2 U13.37(LSET)
NetR190_1: R190.1 TP41.1 U13.34(PWM)
NetR194_1: R194.1 U13.32(BOOTR)

Not connected (* = marked no-connect by the designer): U11 6(NC) 31(NC) 41(NC); U12 6(NC) 31(NC) 41(NC); U13 6(NC) 31(NC) 41(NC)

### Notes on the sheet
- VOUTA- Phase-4
- The 0 Ohms for the ACSP, APWM, and ATAO are optional they do not need to be populated. These are put in place for testing purposes. Same with the test point on the PWM signal
- (near C234) The IOUT and VREF jumper is only needed if you need to test the current capability of the controller.
- VOUTA- Phase-5
- VOUTA- Phase-6

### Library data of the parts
C219 C235 C251 = CMP-0006673-2: as C171 on sheet EVRHC008_VOUT_A_Phases 1-2-3
C220 C225 C236 C241 C252 C257 = CMP-0012242-3: as C172 on sheet EVRHC008_VOUT_A_Phases 1-2-3
C221-C224 C237-C240 C253-C256 = CMP-0008932-2: as C173-C176 on sheet EVRHC008_VOUT_A_Phases 1-2-3
C226 C242 C258 = CMP-0086485-1: as C178 on sheet EVRHC008_VOUT_A_Phases 1-2-3
C227-C229 C243-C245 C259-C261 = CMP-0008293-2: as C179 on sheet EVRHC008_VOUT_A_Phases 1-2-3
C230 C234 C248 C250 C264 C266 = CMP-0006356-2: as C182 on sheet EVRHC008_VOUT_A_Phases 1-2-3
C231 C232 C246 C247 C262 C263 = CMP-0006263-2: as C183 on sheet EVRHC008_VOUT_A_Phases 1-2-3
C233 C249 C265 = CMP-0006233-2: as C185 on sheet EVRHC008_VOUT_A_Phases 1-2-3
J40-J42 = CMP-0075405-3: as J32 on sheet EVRHC008_VOUT_A_Phases 1-2-3
L5-L7 = CMP-0060908-1: as L2 on sheet EVRHC008_VOUT_A_Phases 1-2-3
R171 R179 R187 = CMP-0025743-4: as R147 on sheet EVRHC008_VOUT_A_Phases 1-2-3
R172 R174 R175 R180 R182 R184 R188 R190 R192 = CMP-0026822-3: as R148 on sheet EVRHC008_VOUT_A_Phases 1-2-3
R173 R181 R189 = CMP-0085489-1: as R149 on sheet EVRHC008_VOUT_A_Phases 1-2-3
R176 R183 R191 = CMP-0026898-3: as R152 on sheet EVRHC008_VOUT_A_Phases 1-2-3
R177 R185 R193 = CMP-0026822-3: as R153 on sheet EVRHC008_VOUT_A_Phases 1-2-3
R178 R186 R194 = CMP-0026822-3: as R154 on sheet EVRHC008_VOUT_A_Phases 1-2-3
TP37 TP39 TP41 = CMP-0055144-1: as TP31 on sheet EVRHC008_VOUT_A_Phases 1-2-3
U11-U13 = CMP-0085794-1: as U8 on sheet EVRHC008_VOUT_A_Phases 1-2-3

## Sheet EVRHC008_VOUT_B_Phases 1-2.SchDoc
size 431 x 279 mm; Date: Not shown in title block; ApprovedBy: Not shown in title block; CheckedBy: Not shown in title block; Author: Not shown in title block; CompanyName: Not shown in title block; Engineer: Not shown in title block; Organization: Not shown in title block; Address1: Not shown in title block; Address2: Not shown in title block; Address3: Not shown in title block; Address4: Not shown in title block; DocumentNumber: 6; Revision: Use project parameter SCH_Rev; SheetNumber: 6; SheetTotal: 17; PageSetup: Record=PageOptions¦CenterHorizontal=True¦CenterVertical=True¦PrintScale=1.00¦XCorrection=1.00¦YCorrection=1.00¦PrintKind=0¦BorderSize=5000000¦LeftOffset=0¦BottomOffset=0¦Orientation=2¦PaperLength=1000¦PaperWidth=1000¦Scale=100¦PaperSource=15¦PrintQuality=600¦MediaType=1¦DitherType=10¦PaperKind=Letter¦PrintScaleMode=1
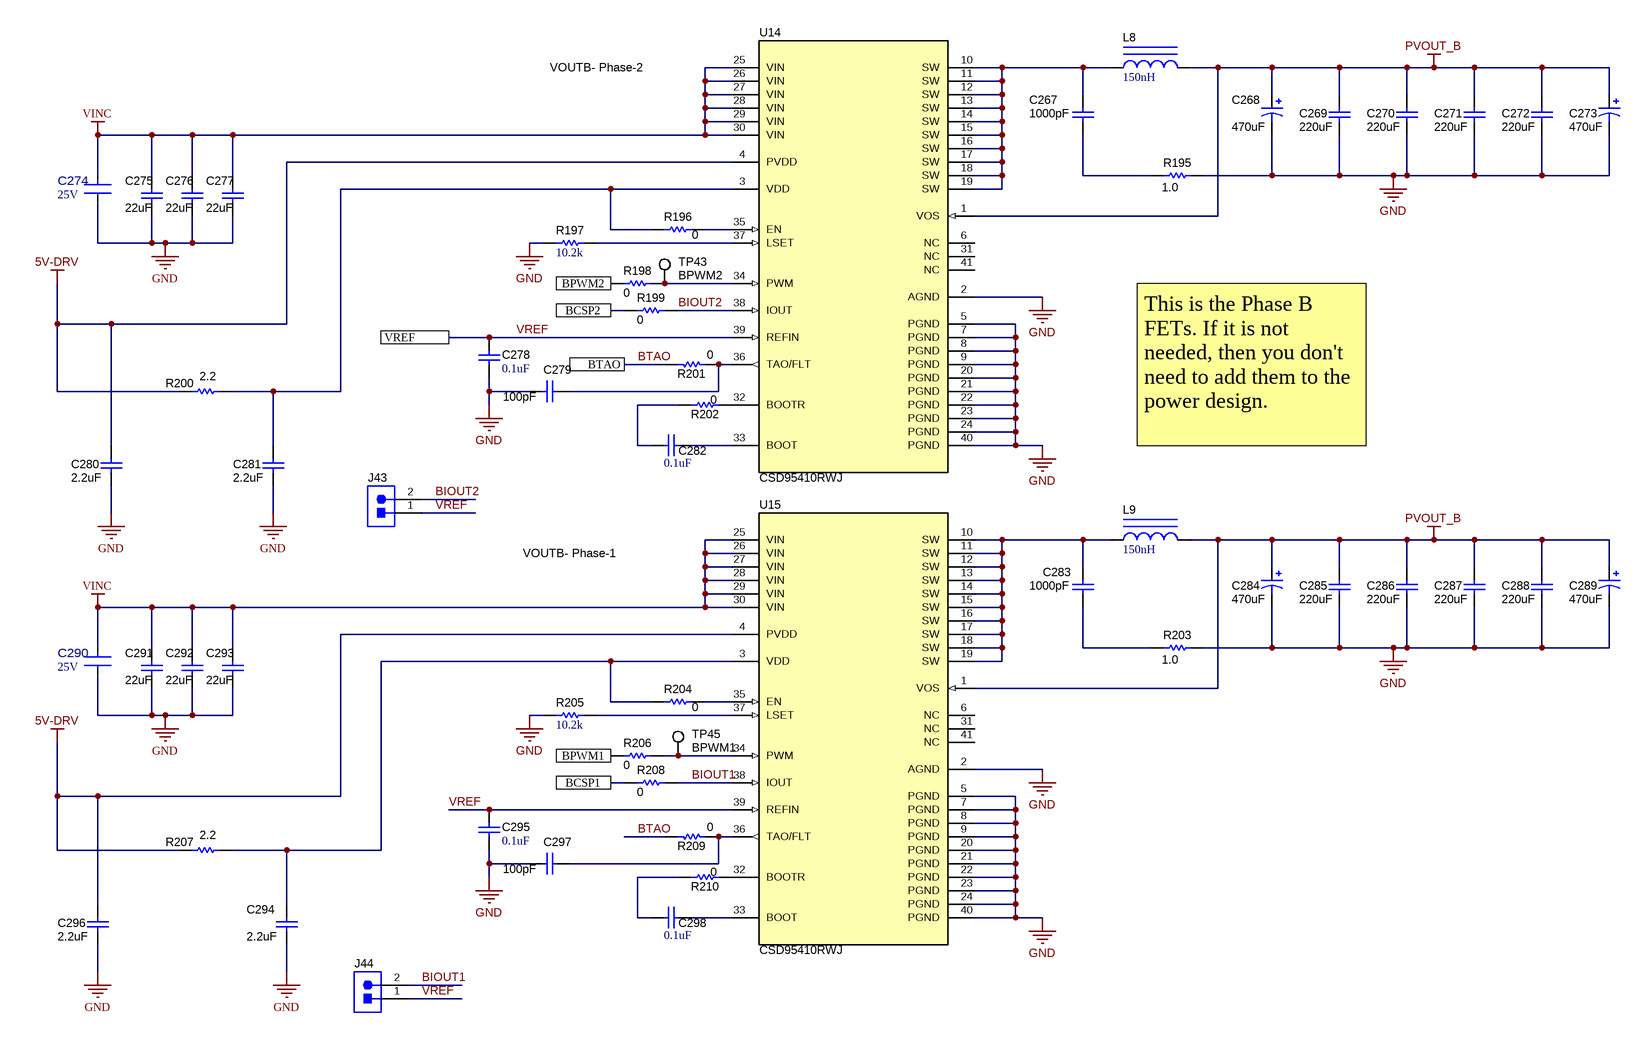
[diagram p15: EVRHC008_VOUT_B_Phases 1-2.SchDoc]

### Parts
C267  ValueDisplayed: 1000pF  [0402S]  (hidden comment: GRM155R71H102KA01D)
C268  ValueDisplayed: 470uF  [GX_2TERM]  (hidden comment: EEF-GX0E471R)
C269  ValueDisplayed: 220uF  [1206_190L]  (hidden comment: GRM31CR60G227ME11L)
C270  ValueDisplayed: 220uF  [1206_190L]  (hidden comment: GRM31CR60G227ME11L)
C271  ValueDisplayed: 220uF  [1206_190L]  (hidden comment: GRM31CR60G227ME11L)
C272  ValueDisplayed: 220uF  [1206_190L]  (hidden comment: GRM31CR60G227ME11L)
C273  ValueDisplayed: 470uF  [GX_2TERM]  (hidden comment: EEF-GX0E471R)
C274  VDC_V: 25V  [FP-GRM155C81E105KE11D_0402-MFG]  (hidden comment: GRM155C81E105KE11D)
C275  ValueDisplayed: 22uF  [0805L]  (hidden comment: Capacitor)
C276  ValueDisplayed: 22uF  [0805L]  (hidden comment: Capacitor)
C277  ValueDisplayed: 22uF  [0805L]  (hidden comment: Capacitor)
C278  ValueDisplayed: 0.1uF  [0402S]  (hidden comment: GCM155R71H104KE02D)
C279  ValueDisplayed: 100pF  [0402S]  (hidden comment: Capacitor)
C280  ValueDisplayed: 2.2uF  [0402S]  (hidden comment: Capacitor)
C281  ValueDisplayed: 2.2uF  [0402S]  (hidden comment: Capacitor)
C282  ValueDisplayed: 0.1uF  [0402S]  (hidden comment: GCM155R71H104KE02D)
C283  ValueDisplayed: 1000pF  [0402S]  (hidden comment: GRM155R71H102KA01D)
C284  ValueDisplayed: 470uF  [GX_2TERM]  (hidden comment: EEF-GX0E471R)
C285  ValueDisplayed: 220uF  [1206_190L]  (hidden comment: GRM31CR60G227ME11L)
C286  ValueDisplayed: 220uF  [1206_190L]  (hidden comment: GRM31CR60G227ME11L)
C287  ValueDisplayed: 220uF  [1206_190L]  (hidden comment: GRM31CR60G227ME11L)
C288  ValueDisplayed: 220uF  [1206_190L]  (hidden comment: GRM31CR60G227ME11L)
C289  ValueDisplayed: 470uF  [GX_2TERM]  (hidden comment: EEF-GX0E471R)
C290  VDC_V: 25V  [FP-GRM155C81E105KE11D_0402-MFG]  (hidden comment: GRM155C81E105KE11D)
C291  ValueDisplayed: 22uF  [0805L]  (hidden comment: Capacitor)
C292  ValueDisplayed: 22uF  [0805L]  (hidden comment: Capacitor)
C293  ValueDisplayed: 22uF  [0805L]  (hidden comment: Capacitor)
C294  ValueDisplayed: 2.2uF  [0402S]  (hidden comment: Capacitor)
C295  ValueDisplayed: 0.1uF  [0402S]  (hidden comment: GCM155R71H104KE02D)
C296  ValueDisplayed: 2.2uF  [0402S]  (hidden comment: Capacitor)
C297  ValueDisplayed: 100pF  [0402S]  (hidden comment: Capacitor)
C298  ValueDisplayed: 0.1uF  [0402S]  (hidden comment: GCM155R71H104KE02D)
J43  TSW-102-07-G-S  [TSW-102-07-G-S]  (value not drawn)
J44  TSW-102-07-G-S  [TSW-102-07-G-S]  (value not drawn)
L8  ValueDisplayed: 150nH  [SLR1050]  (hidden comment: SLR1050A-151KEB)
L9  ValueDisplayed: 150nH  [SLR1050]  (hidden comment: SLR1050A-151KEB)
R195  ValueDisplayed: 1.0  [0603S]  (hidden comment: CRCW06031R00JNEA)
R196  ValueDisplayed: 0  [0402S]  (hidden comment: CRCW04020000Z0ED)
R197  ValueDisplayed: 10.2k  [0402S]  (hidden comment: ERA-2AEB1022X)
R198  ValueDisplayed: 0  [0402S]  (hidden comment: CRCW04020000Z0ED)
R199  ValueDisplayed: 0  [0402S]  (hidden comment: CRCW04020000Z0ED)
R200  value 2.2  [0402S]  (hidden comment: CRCW04022R20JNED)
R201  ValueDisplayed: 0  [0402S]  (hidden comment: CRCW04020000Z0ED)
R202  value 0  [0402S]  (hidden comment: CRCW04020000Z0ED)
R203  ValueDisplayed: 1.0  [0603S]  (hidden comment: CRCW06031R00JNEA)
R204  ValueDisplayed: 0  [0402S]  (hidden comment: CRCW04020000Z0ED)
R205  ValueDisplayed: 10.2k  [0402S]  (hidden comment: ERA-2AEB1022X)
R206  ValueDisplayed: 0  [0402S]  (hidden comment: CRCW04020000Z0ED)
R207  value 2.2  [0402S]  (hidden comment: CRCW04022R20JNED)
R208  ValueDisplayed: 0  [0402S]  (hidden comment: CRCW04020000Z0ED)
R209  ValueDisplayed: 0  [0402S]  (hidden comment: CRCW04020000Z0ED)
R210  value 0  [0402S]  (hidden comment: CRCW04020000Z0ED)
TP43  BPWM2  [Keystone5007]
TP45  BPWM1  [Keystone5007]
U14  CSD95410RWJ  [RWJ0041A]
U15  CSD95410RWJ  [RWJ0041A]

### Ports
BCSP1, BCSP2, BPWM1, BPWM2, BTAO, VREF

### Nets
5V-DRV: C280.1 C296.1 R200.1 R207.1 U14.4(PVDD) U15.4(PVDD)
GND: C268.2(-) C269.2 C270.2 C271.2 C272.2 C273.2(-) C274.2 C275.2 C276.2 C277.2 C278.1 C279.1 C280.2 C281.2 C284.2(-) C285.2 C286.2 C287.2 C288.2 C289.2(-) C290.2 C291.2 C292.2 C293.2 C294.2 C295.1 C296.2 C297.1 R195.1 R197.1 R203.1 R205.1 U14.2(AGND) U14.5(PGND) U14.7(PGND) U14.8(PGND) U14.9(PGND) U14.20(PGND) U14.21(PGND) U14.22(PGND) U14.23(PGND) U14.24(PGND) U14.40(PGND) U15.2(AGND) U15.5(PGND) U15.7(PGND) U15.8(PGND) U15.9(PGND) U15.20(PGND) U15.21(PGND) U15.22(PGND) U15.23(PGND) U15.24(PGND) U15.40(PGND)
PVOUT_B: C268.1(+) C269.1 C270.1 C271.1 C272.1 C273.1(+) C284.1(+) C285.1 C286.1 C287.1 C288.1 C289.1(+) L8.2 L9.2 U14.1(VOS) U15.1(VOS)
VINC: C274.1 C275.1 C276.1 C277.1 C290.1 C291.1 C292.1 C293.1 U14.25(VIN) U14.26(VIN) U14.27(VIN) U14.28(VIN) U14.29(VIN) U14.30(VIN) U15.25(VIN) U15.26(VIN) U15.27(VIN) U15.28(VIN) U15.29(VIN) U15.30(VIN)
BCSP1: R208.2 ; port BCSP1
BCSP2: R199.2 ; port BCSP2
BIOUT1: J44.2 R208.1 U15.38(IOUT)
BIOUT2: J43.2 R199.1 U14.38(IOUT)
BPWM1: R206.2 ; port BPWM1
BPWM2: R198.2 ; port BPWM2
BTAO: R201.1 R209.1 ; port BTAO
VREF: C278.2 C295.2 J43.1 J44.1 U14.39(REFIN) U15.39(REFIN) ; port VREF
NetC267_1: C267.1 L8.1 U14.10(SW) U14.11(SW) U14.12(SW) U14.13(SW) U14.14(SW) U14.15(SW) U14.16(SW) U14.17(SW) U14.18(SW) U14.19(SW)
NetC267_2: C267.2 R195.2
NetC279_2: C279.2 R201.2 U14.36(TAO/FLT)
NetC281_1: C281.1 R196.2 R200.2 U14.3(VDD)
NetC282_1: C282.1 R202.2
NetC282_2: C282.2 U14.33(BOOT)
NetC283_1: C283.1 L9.1 U15.10(SW) U15.11(SW) U15.12(SW) U15.13(SW) U15.14(SW) U15.15(SW) U15.16(SW) U15.17(SW) U15.18(SW) U15.19(SW)
NetC283_2: C283.2 R203.2
NetC294_1: C294.1 R204.2 R207.2 U15.3(VDD)
NetC297_2: C297.2 R209.2 U15.36(TAO/FLT)
NetC298_1: C298.1 R210.2
NetC298_2: C298.2 U15.33(BOOT)
NetR196_1: R196.1 U14.35(EN)
NetR197_2: R197.2 U14.37(LSET)
NetR198_1: R198.1 TP43.1 U14.34(PWM)
NetR202_1: R202.1 U14.32(BOOTR)
NetR204_1: R204.1 U15.35(EN)
NetR205_2: R205.2 U15.37(LSET)
NetR206_1: R206.1 TP45.1 U15.34(PWM)
NetR210_1: R210.1 U15.32(BOOTR)

Not connected (* = marked no-connect by the designer): U14 6(NC) 31(NC) 41(NC); U15 6(NC) 31(NC) 41(NC)

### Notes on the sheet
- VOUTB- Phase-2
- This is the Phase B FETs. If it is not needed, then you don't need to add them to the power design.
- VOUTB- Phase-1

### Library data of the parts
C267 C283 = CMP-0006673-2: as C171 on sheet EVRHC008_VOUT_A_Phases 1-2-3
C268 C273 C284 C289 = CMP-0012242-3: as C172 on sheet EVRHC008_VOUT_A_Phases 1-2-3
C269-C272 C285-C288 = CMP-0008932-2: as C173-C176 on sheet EVRHC008_VOUT_A_Phases 1-2-3
C274 C290 = CMP-0086485-1: as C178 on sheet EVRHC008_VOUT_A_Phases 1-2-3
C275-C277 C291-C293 = CMP-0008293-2: as C179 on sheet EVRHC008_VOUT_A_Phases 1-2-3
C278 C282 C295 C298 = CMP-0006356-2: as C182 on sheet EVRHC008_VOUT_A_Phases 1-2-3
C279 C297 = CMP-0006233-2: as C185 on sheet EVRHC008_VOUT_A_Phases 1-2-3
C280 C281 C294 C296 = CMP-0006263-2: as C183 on sheet EVRHC008_VOUT_A_Phases 1-2-3
J43 J44 = CMP-0075405-3: as J32 on sheet EVRHC008_VOUT_A_Phases 1-2-3
L8 L9 = CMP-0060908-1: as L2 on sheet EVRHC008_VOUT_A_Phases 1-2-3
R195 R203 = CMP-0025743-4: as R147 on sheet EVRHC008_VOUT_A_Phases 1-2-3
R196 R198 R199 R204 R206 R208 = CMP-0026822-3: as R148 on sheet EVRHC008_VOUT_A_Phases 1-2-3
R197 R205 = CMP-0085489-1: as R149 on sheet EVRHC008_VOUT_A_Phases 1-2-3
R200 R207 = CMP-0026898-3: as R152 on sheet EVRHC008_VOUT_A_Phases 1-2-3
R201 R209 = CMP-0026822-3: as R153 on sheet EVRHC008_VOUT_A_Phases 1-2-3
R202 R210 = CMP-0026822-3: as R154 on sheet EVRHC008_VOUT_A_Phases 1-2-3
TP43 TP45 = CMP-0055144-1: as TP31 on sheet EVRHC008_VOUT_A_Phases 1-2-3
U14 U15 = CMP-0085794-1: as U8 on sheet EVRHC008_VOUT_A_Phases 1-2-3

## Sheet Hardware.SchDoc
size 431 x 279 mm; Date: Not shown in title block; ApprovedBy: Not shown in title block; CheckedBy: Not shown in title block; Author: Not shown in title block; CompanyName: Not shown in title block; Engineer: Not shown in title block; Organization: Not shown in title block; Address1: Not shown in title block; Address2: Not shown in title block; Address3: Not shown in title block; Address4: Not shown in title block; DocumentNumber: 17; Revision: Use project parameter SCH_Rev; SheetNumber: 17; SheetTotal: 17; PageSetup: Record=PageOptions¦CenterHorizontal=True¦CenterVertical=True¦PrintScale=1.00¦XCorrection=1.00¦YCorrection=1.00¦PrintKind=0¦BorderSize=5000000¦LeftOffset=0¦BottomOffset=0¦Orientation=2¦PaperLength=1000¦PaperWidth=1000¦Scale=100¦PaperSource=15¦PrintQuality=600¦MediaType=1¦DitherType=10¦PaperKind=Letter¦PrintScaleMode=1
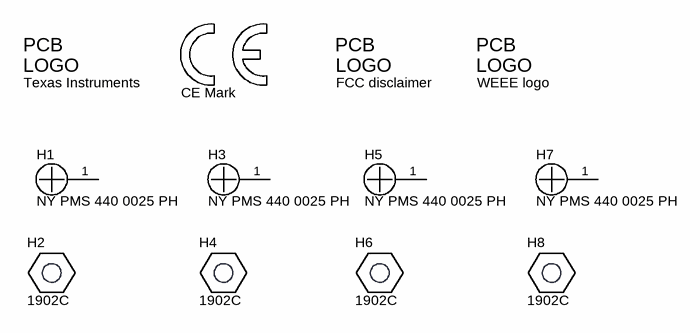
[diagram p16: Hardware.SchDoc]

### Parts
H1  NY PMS 440 0025 PH  [NY PMS 440 0025 PH]
H2  1902C  [Keystone_1902C]
H3  NY PMS 440 0025 PH  [NY PMS 440 0025 PH]
H4  1902C  [Keystone_1902C]
H5  NY PMS 440 0025 PH  [NY PMS 440 0025 PH]
H6  1902C  [Keystone_1902C]
H7  NY PMS 440 0025 PH  [NY PMS 440 0025 PH]
H8  1902C  [Keystone_1902C]
Logo1  CE Mark  [CE_Mark_5mm]  (no BOM)
Logo2  Texas Instruments  [TI_Stacked_Overlay_Small]  (no BOM)
Logo3  FCC disclaimer  [FCC_disclaimer]  (no BOM)
Logo4  WEEE logo  [WEEE_Minimum]  (no BOM)

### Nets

Not connected (* = marked no-connect by the designer): H1 1; H3 1; H5 1; H7 1

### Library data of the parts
H1 H3 H5 H7 = CMP-0003617-1: Machine Screw, Round, #4-40 x 1/4, Nylon, Philips panhead; Manufacturer: B&F Fastener Supply; CompType: Hardware
H2 H4 H6 H8 = CMP-0003610-1: Standoff, Hex, 0.5"L #4-40 Nylon; Manufacturer: Keystone; CompType: Hardware
Logo1 = CMP-0074844-1: SymbolCreator: a0412235
Logo2 = CMP-0074838-1: Texas Instrument Corporate Signature; SymbolCreator: a0412235; Lib Reference: TI_Logo; Library Reference: Logo
Logo3 = CMP-0074847-1: FCC_disclaimer; Library Reference: Logo
Logo4 = CMP-0074769-1

## Sheet Block Diagram.SchDoc
size 431 x 279 mm; Date: Not shown in title block; ApprovedBy: Not shown in title block; CheckedBy: Not shown in title block; Author: Not shown in title block; CompanyName: Not shown in title block; Engineer: Not shown in title block; Organization: Not shown in title block; Address1: Not shown in title block; Address2: Not shown in title block; Address3: Not shown in title block; Address4: Not shown in title block; DocumentNumber: 1; Revision: Use project parameter SCH_Rev; SheetNumber: 1; SheetTotal: 17; PageSetup: Record=PageOptions¦CenterHorizontal=True¦CenterVertical=True¦PrintScale=1.00¦XCorrection=1.00¦YCorrection=1.00¦PrintKind=0¦BorderSize=5000000¦LeftOffset=0¦BottomOffset=0¦Orientation=2¦PaperLength=1000¦PaperWidth=1000¦Scale=100¦PaperSource=15¦PrintQuality=600¦MediaType=1¦DitherType=10¦PaperKind=Letter¦PrintScaleMode=1
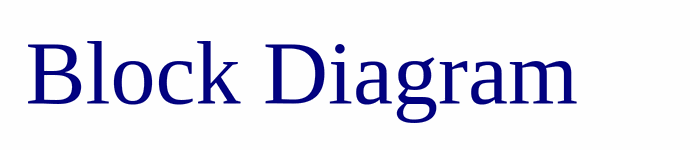
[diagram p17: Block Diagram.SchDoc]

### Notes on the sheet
- Block Diagram

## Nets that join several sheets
3.3V-Con: EVRHC008_ CONTROLLER_6X6 (12 pins), EVRHC008_ Dynamic Load (S3.1 S3.2 S3.3 S3.4), EVRHC008_Aux Power (C7.1 R5.2 TP6.1), EVRHC008_HelperCkts and Indicators (10 pins)
5V-AUX: EVRHC008_ Dynamic Load (10 pins), EVRHC008_Aux Power (5 pins)
5V-DRV: EVRHC008_Aux Power (R1.2 TP2.1), EVRHC008_VOUT_A_Phases 1-2-3 (9 pins), EVRHC008_VOUT_A_Phases 4-5-6 (9 pins), EVRHC008_VOUT_B_Phases 1-2 (6 pins)
5V_MODULE: TPS6508641_Project_TPS65086 (J19.1 J19.3), TPSM5D1806 Multi Phase (27 pins)
BUCK1_OUT: TPS6508641_Project_Buck12 (13 pins), TPS6508641_Project_TPS65086 (J19.5 J19.7)
BUCK6_OUT: TPS6508641_Project_Buck6 (13 pins), TPS6508641_Project_TPS65086 (5 pins)
GND: TPS6508641_Project_Buck12 (28 pins), TPS6508641_Project_Buck6 (15 pins), TPS6508641_Project_Buck345 (17 pins), TPS6508641_Project_TPS65086 (30 pins), TPS6508641_Support_Devices (7 pins), TPSM5D1806 IND (52 pins), TPSM5D1806 Multi Phase (28 pins), EVRHC008_  Filters (152 pins), EVRHC008_ CONTROLLER_6X6 (24 pins), EVRHC008_ Dynamic Load (85 pins), EVRHC008_Aux Power (15 pins), EVRHC008_HelperCkts and Indicators (18 pins), EVRHC008_VOUT_A_Phases 1-2-3 (81 pins), EVRHC008_VOUT_A_Phases 4-5-6 (81 pins), EVRHC008_VOUT_B_Phases 1-2 (54 pins)
LDO3P3: TPS6508641_Project_TPS65086 (8 pins), TPS6508641_Support_Devices (7 pins)
PVOUT_A: EVRHC008_  Filters (70 pins), EVRHC008_ CONTROLLER_6X6 (R8.2), EVRHC008_ Dynamic Load (118 pins), EVRHC008_HelperCkts and Indicators (NT3.1), EVRHC008_VOUT_A_Phases 1-2-3 (24 pins), EVRHC008_VOUT_A_Phases 4-5-6 (24 pins)
PVOUT_B: EVRHC008_  Filters (75 pins), EVRHC008_ CONTROLLER_6X6 (R10.2), EVRHC008_HelperCkts and Indicators (NT4.1), EVRHC008_VOUT_B_Phases 1-2 (16 pins)
VCCAUX: TPS6508641_Project_TPS65086 (C346.1 C347.1 R214.2 U16.17), TPS6508641_Support_Devices (J31.1 TP74.1)
VIN: TPS6508641_Project_Buck12 (6 pins), TPS6508641_Project_Buck6 (C299.1 Q10.1 Q10.2), TPS6508641_Project_TPS65086 (6 pins), TPSM5D1806 IND (20 pins), TPSM5D1806 Multi Phase (9 pins), EVRHC008_  Filters (5 pins), EVRHC008_Aux Power (C4.1 R4.2 U2.2)
VINC: EVRHC008_  Filters (7 pins), EVRHC008_VOUT_A_Phases 1-2-3 (30 pins), EVRHC008_VOUT_A_Phases 4-5-6 (30 pins), EVRHC008_VOUT_B_Phases 1-2 (20 pins)
VTT: TPS6508641_Project_TPS65086 (C345.1 C397.1 U16.47 U16.48), TPS6508641_Support_Devices (J30.1 TP71.1)
ACSP1: EVRHC008_ CONTROLLER_6X6 (U3.23), EVRHC008_VOUT_A_Phases 1-2-3 (R151.2)
ACSP2: EVRHC008_ CONTROLLER_6X6 (U3.24), EVRHC008_VOUT_A_Phases 1-2-3 (R160.2)
ACSP3: EVRHC008_ CONTROLLER_6X6 (U3.25), EVRHC008_VOUT_A_Phases 1-2-3 (R168.2)
ACSP4: EVRHC008_ CONTROLLER_6X6 (U3.26), EVRHC008_VOUT_A_Phases 4-5-6 (R175.2)
ACSP5: EVRHC008_ CONTROLLER_6X6 (U3.27), EVRHC008_VOUT_A_Phases 4-5-6 (R184.2)
ACSP6: EVRHC008_ CONTROLLER_6X6 (U3.28), EVRHC008_VOUT_A_Phases 4-5-6 (R192.2)
APWM1: EVRHC008_ CONTROLLER_6X6 (U3.8), EVRHC008_VOUT_A_Phases 1-2-3 (R150.2)
APWM2: EVRHC008_ CONTROLLER_6X6 (U3.7), EVRHC008_VOUT_A_Phases 1-2-3 (R158.2)
APWM3: EVRHC008_ CONTROLLER_6X6 (U3.6), EVRHC008_VOUT_A_Phases 1-2-3 (R166.2)
APWM4: EVRHC008_ CONTROLLER_6X6 (U3.5), EVRHC008_VOUT_A_Phases 4-5-6 (R174.2)
APWM5: EVRHC008_ CONTROLLER_6X6 (U3.4), EVRHC008_VOUT_A_Phases 4-5-6 (R182.2)
APWM6: EVRHC008_ CONTROLLER_6X6 (U3.3), EVRHC008_VOUT_A_Phases 4-5-6 (R190.2)
ATAO: EVRHC008_ CONTROLLER_6X6 (R27.2), EVRHC008_VOUT_A_Phases 1-2-3 (R153.1 R161.1 R169.1), EVRHC008_VOUT_A_Phases 4-5-6 (R177.1 R185.1 R193.1)
BCSP1: EVRHC008_ CONTROLLER_6X6 (U3.30), EVRHC008_VOUT_B_Phases 1-2 (R208.2)
BCSP2: EVRHC008_ CONTROLLER_6X6 (U3.29), EVRHC008_VOUT_B_Phases 1-2 (R199.2)
BOOT1: TPS6508641_Project_Buck12 (C308.1), TPS6508641_Project_TPS65086 (U16.35)
BOOT2: TPS6508641_Project_Buck12 (C318.1), TPS6508641_Project_TPS65086 (U16.5)
BOOT6: TPS6508641_Project_Buck6 (C300.1), TPS6508641_Project_TPS65086 (U16.41)
BPWM1: EVRHC008_ CONTROLLER_6X6 (U3.1), EVRHC008_VOUT_B_Phases 1-2 (R206.2)
BPWM2: EVRHC008_ CONTROLLER_6X6 (U3.2), EVRHC008_VOUT_B_Phases 1-2 (R198.2)
BTAO: EVRHC008_ CONTROLLER_6X6 (R25.2), EVRHC008_VOUT_B_Phases 1-2 (R201.1 R209.1)
DRVH1: TPS6508641_Project_Buck12 (Q11.3), TPS6508641_Project_TPS65086 (U16.33)
DRVH2: TPS6508641_Project_Buck12 (Q12.3), TPS6508641_Project_TPS65086 (U16.3)
DRVH6: TPS6508641_Project_Buck6 (Q10.3), TPS6508641_Project_TPS65086 (U16.43)
DRVL1: TPS6508641_Project_Buck12 (Q11.5), TPS6508641_Project_TPS65086 (U16.37)
DRVL2: TPS6508641_Project_Buck12 (Q12.5), TPS6508641_Project_TPS65086 (U16.7)
DRVL6: TPS6508641_Project_Buck6 (Q10.5), TPS6508641_Project_TPS65086 (U16.39)
EN_VOUT_A_N: EVRHC008_ CONTROLLER_6X6 (5 pins), EVRHC008_HelperCkts and Indicators (R138.1 R142.2)
EN_VOUT_B_N: EVRHC008_ CONTROLLER_6X6 (5 pins), EVRHC008_HelperCkts and Indicators (R137.1 R141.2)
FB3: TPS6508641_Project_Buck345 (NT13.1), TPS6508641_Project_TPS65086 (U16.12)
FB4: TPS6508641_Project_Buck345 (NT14.1), TPS6508641_Project_TPS65086 (U16.23)
FB5: TPS6508641_Project_Buck345 (NT15.1), TPS6508641_Project_TPS65086 (U16.22)
FBVOUT1: TPS6508641_Project_Buck12 (NT10.1), TPS6508641_Project_TPS65086 (U16.29)
FBVOUT2: TPS6508641_Project_Buck12 (NT12.1), TPS6508641_Project_TPS65086 (U16.2)
FBVOUT6: TPS6508641_Project_Buck6 (NT8.1), TPS6508641_Project_TPS65086 (U16.44)
GPO1: TPS6508641_Project_TPS65086 (U16.16), TPS6508641_Support_Devices (J4.1 R223.2 TP73.1)
GPO2: TPS6508641_Project_TPS65086 (U16.26), TPS6508641_Support_Devices (J4.2 R224.2 TP75.1)
GPO3: TPS6508641_Project_TPS65086 (U16.27), TPS6508641_Support_Devices (J4.3 R222.2 TP72.1)
GPO4: TPS6508641_Project_TPS65086 (U16.28), TPS6508641_Support_Devices (J4.4 R225.2 TP76.1)
ILIM1: TPS6508641_Project_Buck12 (R212.1), TPS6508641_Project_TPS65086 (U16.30)
ILIM2: TPS6508641_Project_Buck12 (R213.1), TPS6508641_Project_TPS65086 (U16.64)
ILIM6: TPS6508641_Project_Buck6 (R211.1), TPS6508641_Project_TPS65086 (U16.45)
IRQB: TPS6508641_Project_TPS65086 (J23.6 U16.15), TPS6508641_Support_Devices (J29.2 TP70.1)
LDOA1: TPS6508641_Project_TPS65086 (U16.9), TPS6508641_Support_Devices (C353.1 J1.2)
LDOA2: TPS6508641_Project_TPS65086 (U16.51), TPS6508641_Support_Devices (C354.1 J1.3)
LDOA3: TPS6508641_Project_TPS65086 (U16.49), TPS6508641_Support_Devices (C355.1 J1.1)
NetC82_1: EVRHC008_  Filters (C82.1 R128.1), EVRHC008_ CONTROLLER_6X6 (R26.1)
NetNT1_2: EVRHC008_  Filters (NT1.2), EVRHC008_ CONTROLLER_6X6 (R24.1)
NetNT2_2: EVRHC008_  Filters (NT2.2), EVRHC008_ CONTROLLER_6X6 (R29.1)
NetR38_1: EVRHC008_  Filters (R129.4 TP15.1), EVRHC008_ CONTROLLER_6X6 (R38.1)
SCL: TPS6508641_Project_TPS65086 (J23.3 U16.58), TPS6508641_Support_Devices (J26.9 R226.1 TP78.1)
SDA: TPS6508641_Project_TPS65086 (J23.4 U16.59), TPS6508641_Support_Devices (J26.10 R227.1 TP79.1)
SNS1: TPS6508641_Project_Buck12 (NT9.1), TPS6508641_Project_TPS65086 (U16.36)
SNS2: TPS6508641_Project_Buck12 (NT11.1), TPS6508641_Project_TPS65086 (U16.6)
SNS6: TPS6508641_Project_Buck6 (NT19.1), TPS6508641_Project_TPS65086 (U16.40)
SW1: TPS6508641_Project_Buck12 (C308.2 Q11.4), TPS6508641_Project_TPS65086 (U16.34)
SW2: TPS6508641_Project_Buck12 (C318.2 Q12.4), TPS6508641_Project_TPS65086 (U16.4)
SW6: TPS6508641_Project_Buck6 (C300.2 Q10.4), TPS6508641_Project_TPS65086 (U16.42)
SWA1: TPS6508641_Project_TPS65086 (U16.31), TPS6508641_Support_Devices (C356.1 J1.4)
VOUT_A_RDY: EVRHC008_ CONTROLLER_6X6 (R34.1 U3.12), EVRHC008_HelperCkts and Indicators (R133.1 R143.2 TP29.1)
VOUT_B_RDY: EVRHC008_ CONTROLLER_6X6 (R35.1 U3.16), EVRHC008_HelperCkts and Indicators (R135.1 R140.2 TP30.1)
VR_FAULT#: EVRHC008_ CONTROLLER_6X6 (R36.1 U3.33), EVRHC008_HelperCkts and Indicators (R136.1 R139.2 TP28.1)
VREF: EVRHC008_ CONTROLLER_6X6 (R14.1 R17.2 R18.1), EVRHC008_VOUT_A_Phases 1-2-3 (9 pins), EVRHC008_VOUT_A_Phases 4-5-6 (9 pins), EVRHC008_VOUT_B_Phases 1-2 (6 pins)
VSN_VOUT_A: EVRHC008_  Filters (J9.122), EVRHC008_ CONTROLLER_6X6 (5 pins)
VSN_VOUT_B: EVRHC008_  Filters (J10.122), EVRHC008_ CONTROLLER_6X6 (5 pins)
VSP_VOUT_A: EVRHC008_  Filters (J9.121), EVRHC008_ CONTROLLER_6X6 (5 pins)
VSP_VOUT_B: EVRHC008_  Filters (J10.121), EVRHC008_ CONTROLLER_6X6 (5 pins)

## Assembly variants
001: not fitted C171 C182 C185 C187 C199 C201 C203 C216 C217 C219 C230 C233 C235 C248 C249 C251 C264 C265 C267 C278 C279 C283 C295 C297 C302 C417 C418 R147 R155 R163 R171 R179 R187 R195 R203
